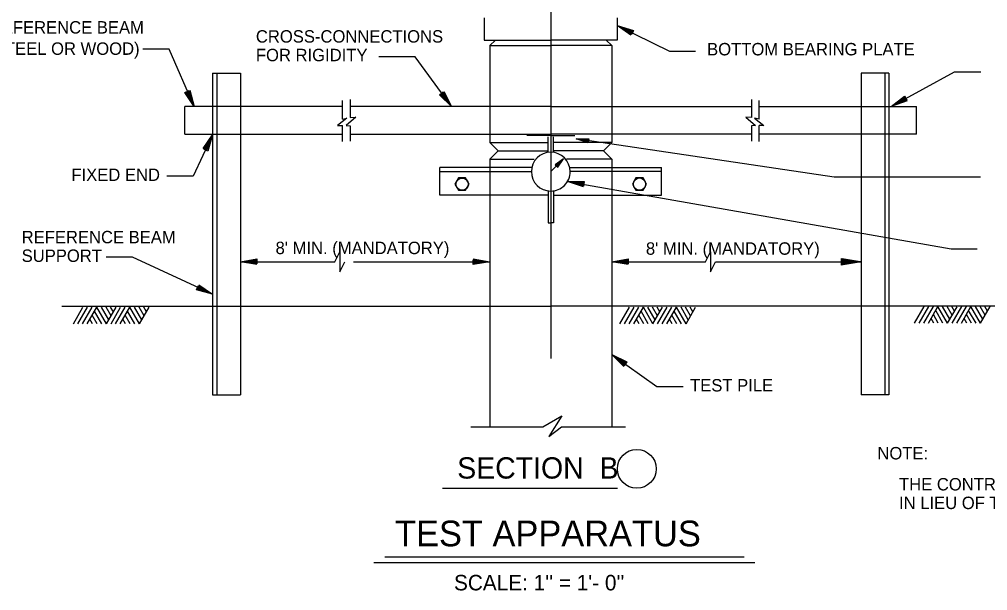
# Model space of a CAD drawing. Extents: x 22378.6 to 22422.6, y 22377.7 to 22411.7.
# Drawn here: x 22398.72 to 22409.64, y 22397.23 to 22403.67 of the extents above; entities that cross this region are included whole.
import ezdxf

# ---------------------------------------------------------------- set-up
doc = ezdxf.new("R2010")
doc.units = 0
for name, color, linetype in [('Level 1', 7, 'Continuous'), ('Level 10', 7, 'Continuous'), ('Level 2', 7, 'Continuous'), ('Level 3', 7, 'Continuous'), ('Level 4', 7, 'Continuous'), ('Level 7', 7, 'Continuous')]:
    doc.layers.add(name, color=color, linetype=linetype)

msp = doc.modelspace()

# ---------------------------------------------------------------- linework, layer by layer
at = {"layer": 'Level 1'}
for p, q in [((22404.71, 22409.083), (22404.71, 22399.845)), ((22405.46, 22403.6), (22405.46, 22403.6)), ((22405.507, 22403.577), (22405.507, 22403.577)), ((22400.667, 22402.734), (22400.667, 22402.734)), ((22402.36, 22402.544), (22402.36, 22402.755)), ((22402.447, 22402.765), (22402.447, 22402.562)), ((22406.972, 22402.765), (22406.972, 22402.562)), ((22407.06, 22402.544), (22407.06, 22402.755)), ((22400.688, 22402.686), (22400.688, 22402.686)), ((22403.56, 22402.728), (22403.56, 22402.728)), ((22403.591, 22402.686), (22403.591, 22402.686)), ((22408.548, 22402.686), (22408.548, 22402.686)), ((22408.594, 22402.711), (22408.594, 22402.711)), ((22402.41, 22402.556), (22402.307, 22402.471)), ((22402.36, 22402.544), (22402.41, 22402.556)), ((22402.511, 22402.568), (22402.402, 22402.471)), ((22402.447, 22402.562), (22402.511, 22402.568)), ((22406.909, 22402.568), (22407.018, 22402.471)), ((22406.972, 22402.562), (22406.909, 22402.568)), ((22407.06, 22402.544), (22407.009, 22402.556)), ((22407.009, 22402.556), (22407.113, 22402.471)), ((22402.307, 22402.471), (22402.36, 22402.473)), ((22402.36, 22402.292), (22402.36, 22402.473)), ((22402.402, 22402.471), (22402.447, 22402.468)), ((22402.447, 22402.468), (22402.447, 22402.297)), ((22407.018, 22402.471), (22406.972, 22402.468)), ((22406.972, 22402.468), (22406.972, 22402.297)), ((22407.06, 22402.292), (22407.06, 22402.473)), ((22407.113, 22402.471), (22407.06, 22402.473)), ((22400.875, 22402.319), (22400.875, 22402.319)), ((22400.897, 22402.366), (22400.897, 22402.366)), ((22404.996, 22402.32), (22404.996, 22402.32)), ((22405.034, 22402.315), (22405.034, 22402.315)), ((22404.022, 22402.28), (22404.669, 22402.28)), ((22405.397, 22402.28), (22404.749, 22402.28)), ((22404.022, 22402.093), (22404.524, 22402.093)), ((22404.854, 22402.096), (22404.761, 22402.03)), ((22404.764, 22402.029), (22404.836, 22402.081)), ((22404.854, 22402.096), (22404.774, 22402.016)), ((22404.836, 22402.081), (22404.776, 22402.021)), ((22404.839, 22402.079), (22404.779, 22402.018)), ((22404.787, 22402.006), (22404.839, 22402.079)), ((22404.788, 22402.003), (22404.854, 22402.096)), ((22405.397, 22402.093), (22404.888, 22402.093)), ((22404.761, 22402.03), (22404.788, 22402.003)), ((22404.774, 22402.019), (22404.764, 22402.029)), ((22404.767, 22402.029), (22404.82, 22402.067)), ((22404.776, 22402.021), (22404.767, 22402.029)), ((22404.771, 22402.028), (22404.797, 22402.048)), ((22404.776, 22402.024), (22404.771, 22402.028)), ((22404.82, 22402.067), (22404.776, 22402.024)), ((22404.797, 22402.048), (22404.776, 22402.027)), ((22404.777, 22402.016), (22404.787, 22402.006)), ((22404.779, 22402.018), (22404.787, 22402.01)), ((22404.825, 22402.062), (22404.782, 22402.018)), ((22404.782, 22402.018), (22404.787, 22402.013)), ((22404.806, 22402.039), (22404.785, 22402.018)), ((22404.787, 22402.01), (22404.825, 22402.062)), ((22404.787, 22402.013), (22404.806, 22402.039)), ((22403.67, 22401.881), (22403.63, 22401.811)), ((22403.75, 22401.881), (22403.67, 22401.881)), ((22403.79, 22401.811), (22403.75, 22401.881)), ((22405.67, 22401.881), (22405.63, 22401.812)), ((22405.75, 22401.881), (22405.67, 22401.881)), ((22405.79, 22401.812), (22405.75, 22401.881)), ((22403.63, 22401.811), (22403.67, 22401.742)), ((22403.75, 22401.742), (22403.79, 22401.811)), ((22404.899, 22401.842), (22404.899, 22401.842)), ((22404.95, 22401.833), (22404.95, 22401.833)), ((22405.63, 22401.812), (22405.67, 22401.742)), ((22405.75, 22401.742), (22405.79, 22401.812)), ((22403.67, 22401.742), (22403.75, 22401.742)), ((22405.67, 22401.742), (22405.75, 22401.742)), ((22401.21, 22400.936), (22402.276, 22400.936)), ((22401.21, 22400.936), (22401.21, 22400.936)), ((22401.262, 22400.936), (22401.262, 22400.936)), ((22402.486, 22400.936), (22404.022, 22400.936)), ((22403.97, 22400.936), (22403.97, 22400.936)), ((22404.022, 22400.936), (22404.022, 22400.936)), ((22405.397, 22400.936), (22406.455, 22400.936)), ((22405.397, 22400.936), (22405.397, 22400.936)), ((22405.449, 22400.936), (22405.449, 22400.936)), ((22406.568, 22400.936), (22408.21, 22400.936)), ((22407.985, 22400.974), (22407.985, 22400.899)), ((22407.985, 22400.974), (22408.21, 22400.936)), ((22408.21, 22400.936), (22407.985, 22400.936)), ((22408.21, 22400.936), (22407.985, 22400.899)), ((22407.988, 22400.904), (22408.176, 22400.934)), ((22407.989, 22400.933), (22407.988, 22400.904)), ((22407.99, 22400.967), (22407.989, 22400.94)), ((22407.989, 22400.94), (22408.177, 22400.939)), ((22408.177, 22400.939), (22407.994, 22400.968)), ((22407.994, 22400.968), (22407.994, 22400.943)), ((22407.994, 22400.943), (22408.135, 22400.942)), ((22408.176, 22400.934), (22407.994, 22400.933)), ((22407.994, 22400.933), (22407.994, 22400.909)), ((22407.994, 22400.909), (22408.133, 22400.93)), ((22408.135, 22400.942), (22407.999, 22400.962)), ((22407.999, 22400.962), (22407.999, 22400.948)), ((22407.999, 22400.948), (22408.072, 22400.947)), ((22408.133, 22400.93), (22407.999, 22400.928)), ((22407.999, 22400.928), (22407.999, 22400.914)), ((22407.999, 22400.914), (22408.073, 22400.924)), ((22408.073, 22400.924), (22408.004, 22400.924)), ((22408.004, 22400.924), (22408.004, 22400.919)), ((22408.004, 22400.919), (22408.025, 22400.92)), ((22408.072, 22400.947), (22408.005, 22400.958)), ((22408.005, 22400.958), (22408.005, 22400.952)), ((22408.005, 22400.952), (22408.026, 22400.952)), ((22400.85, 22400.592), (22400.85, 22400.592)), ((22400.897, 22400.57), (22400.897, 22400.57)), ((22399.327, 22400.235), (22399.435, 22400.423)), ((22399.379, 22400.235), (22399.487, 22400.423)), ((22399.431, 22400.235), (22399.539, 22400.423)), ((22399.483, 22400.235), (22399.591, 22400.423)), ((22399.596, 22400.235), (22399.539, 22400.333)), ((22399.648, 22400.235), (22399.565, 22400.378)), ((22399.7, 22400.235), (22399.591, 22400.423)), ((22399.726, 22400.28), (22399.643, 22400.423)), ((22399.752, 22400.325), (22399.695, 22400.423)), ((22399.7, 22400.235), (22399.808, 22400.423)), ((22399.778, 22400.37), (22399.747, 22400.423)), ((22399.752, 22400.235), (22399.86, 22400.423)), ((22399.803, 22400.235), (22399.912, 22400.423)), ((22399.855, 22400.235), (22399.964, 22400.423)), ((22399.968, 22400.235), (22399.912, 22400.333)), ((22400.02, 22400.235), (22399.938, 22400.378)), ((22400.072, 22400.235), (22399.964, 22400.423)), ((22400.098, 22400.28), (22400.016, 22400.423)), ((22400.124, 22400.325), (22400.068, 22400.423)), ((22400.072, 22400.235), (22400.18, 22400.423)), ((22400.15, 22400.37), (22400.12, 22400.423)), ((22405.49, 22400.235), (22405.598, 22400.423)), ((22405.542, 22400.235), (22405.65, 22400.423)), ((22405.594, 22400.235), (22405.702, 22400.423)), ((22405.646, 22400.235), (22405.754, 22400.423)), ((22405.758, 22400.235), (22405.702, 22400.333)), ((22405.81, 22400.235), (22405.728, 22400.378)), ((22405.862, 22400.235), (22405.754, 22400.423)), ((22405.888, 22400.28), (22405.806, 22400.423)), ((22405.914, 22400.325), (22405.858, 22400.423)), ((22405.862, 22400.235), (22405.971, 22400.423)), ((22405.94, 22400.37), (22405.91, 22400.423)), ((22405.914, 22400.235), (22406.023, 22400.423)), ((22405.966, 22400.235), (22406.075, 22400.423)), ((22406.018, 22400.235), (22406.127, 22400.423)), ((22406.131, 22400.235), (22406.075, 22400.333)), ((22406.183, 22400.235), (22406.101, 22400.378)), ((22406.235, 22400.235), (22406.127, 22400.423)), ((22406.261, 22400.28), (22406.179, 22400.423)), ((22406.287, 22400.325), (22406.231, 22400.423)), ((22406.235, 22400.235), (22406.343, 22400.423)), ((22406.313, 22400.37), (22406.283, 22400.423)), ((22408.812, 22400.242), (22408.92, 22400.43)), ((22408.864, 22400.242), (22408.972, 22400.43)), ((22408.916, 22400.242), (22409.024, 22400.43)), ((22408.968, 22400.242), (22409.076, 22400.43)), ((22409.08, 22400.242), (22409.024, 22400.34)), ((22409.132, 22400.242), (22409.05, 22400.385)), ((22409.184, 22400.242), (22409.076, 22400.43)), ((22409.21, 22400.287), (22409.128, 22400.43)), ((22409.236, 22400.332), (22409.18, 22400.43)), ((22409.184, 22400.242), (22409.292, 22400.429)), ((22409.262, 22400.377), (22409.232, 22400.43)), ((22409.236, 22400.242), (22409.344, 22400.43)), ((22409.288, 22400.242), (22409.396, 22400.43)), ((22409.34, 22400.242), (22409.448, 22400.43)), ((22409.453, 22400.242), (22409.396, 22400.34)), ((22409.505, 22400.242), (22409.422, 22400.385)), ((22409.557, 22400.242), (22409.448, 22400.43)), ((22409.583, 22400.287), (22409.5, 22400.43)), ((22409.609, 22400.332), (22409.552, 22400.43)), ((22409.557, 22400.242), (22409.665, 22400.43)), ((22409.635, 22400.377), (22409.604, 22400.43)), ((22399.544, 22400.235), (22399.513, 22400.288)), ((22399.916, 22400.235), (22399.886, 22400.288)), ((22405.707, 22400.235), (22405.676, 22400.288)), ((22406.079, 22400.235), (22406.049, 22400.288)), ((22409.028, 22400.242), (22408.998, 22400.295)), ((22409.401, 22400.242), (22409.37, 22400.295)), ((22405.397, 22399.889), (22405.397, 22399.889)), ((22405.44, 22399.859), (22405.44, 22399.859))]:
    msp.add_line(p, q, dxfattribs=at)
for points in [[(22405.46, 22403.6), (22406.047, 22403.311), (22406.343, 22403.311)], [(22405.614, 22403.489), (22405.46, 22403.6), (22405.641, 22403.545), (22405.618, 22403.497), (22405.507, 22403.577), (22405.63, 22403.539), (22405.615, 22403.509), (22405.551, 22403.555), (22405.618, 22403.534), (22405.612, 22403.521), (22405.598, 22403.532)], [(22400.688, 22402.686), (22400.408, 22403.333), (22400.112, 22403.333)], [(22403.591, 22402.686), (22403.182, 22403.248), (22402.771, 22403.248)], [(22408.548, 22402.686), (22409.264, 22403.077), (22409.56, 22403.077)], [(22400.642, 22402.87), (22400.688, 22402.686), (22400.585, 22402.846), (22400.634, 22402.867), (22400.667, 22402.734), (22400.598, 22402.842), (22400.629, 22402.856), (22400.648, 22402.78), (22400.61, 22402.839), (22400.623, 22402.845), (22400.627, 22402.828)], [(22403.506, 22402.856), (22403.591, 22402.686), (22403.456, 22402.819), (22403.498, 22402.851), (22403.56, 22402.728), (22403.468, 22402.819), (22403.496, 22402.839), (22403.531, 22402.769), (22403.481, 22402.818), (22403.493, 22402.826), (22403.5, 22402.811)], [(22408.727, 22402.749), (22408.548, 22402.686), (22408.697, 22402.803), (22408.723, 22402.757), (22408.594, 22402.711), (22408.695, 22402.791), (22408.711, 22402.761), (22408.637, 22402.735), (22408.693, 22402.778), (22408.699, 22402.766), (22408.683, 22402.76)], [(22400.897, 22402.366), (22400.676, 22401.9), (22400.379, 22401.9)], [(22400.789, 22402.211), (22400.897, 22402.366), (22400.845, 22402.184), (22400.797, 22402.207), (22400.875, 22402.319), (22400.839, 22402.195), (22400.809, 22402.21), (22400.854, 22402.274), (22400.834, 22402.207), (22400.821, 22402.213), (22400.831, 22402.227)], [(22405.131, 22402.277), (22404.996, 22402.32), (22405.138, 22402.323), (22405.132, 22402.283), (22405.034, 22402.315), (22405.131, 22402.316), (22405.127, 22402.291), (22405.071, 22402.309), (22405.124, 22402.31), (22405.122, 22402.299), (22405.11, 22402.303)], [(22409.555, 22401.888), (22407.906, 22401.888), (22404.996, 22402.32)], [(22404.899, 22401.842), (22409.223, 22401.082), (22409.519, 22401.082)], [(22405.078, 22401.779), (22404.899, 22401.842), (22405.088, 22401.84), (22405.079, 22401.788), (22404.95, 22401.833), (22405.079, 22401.832), (22405.073, 22401.798), (22404.999, 22401.824), (22405.069, 22401.823), (22405.067, 22401.809), (22405.051, 22401.815)], [(22400.897, 22400.57), (22399.993, 22400.988), (22399.696, 22400.988)], [(22402.276, 22400.936), (22402.332, 22401.049), (22402.332, 22400.824), (22402.389, 22400.936)], [(22406.455, 22400.936), (22406.511, 22401.049), (22406.511, 22400.824), (22406.568, 22400.936)], [(22401.397, 22400.905), (22401.21, 22400.936), (22401.397, 22400.967), (22401.397, 22400.914), (22401.262, 22400.936), (22401.389, 22400.957), (22401.389, 22400.923), (22401.312, 22400.936), (22401.381, 22400.947), (22401.381, 22400.933), (22401.364, 22400.936)], [(22403.835, 22400.967), (22404.022, 22400.936), (22403.835, 22400.905), (22403.835, 22400.958), (22403.97, 22400.936), (22403.843, 22400.915), (22403.843, 22400.949), (22403.92, 22400.936), (22403.851, 22400.925), (22403.851, 22400.939), (22403.868, 22400.936)], [(22405.584, 22400.905), (22405.397, 22400.936), (22405.584, 22400.967), (22405.584, 22400.914), (22405.449, 22400.936), (22405.576, 22400.957), (22405.576, 22400.923), (22405.499, 22400.936), (22405.568, 22400.947), (22405.568, 22400.933), (22405.551, 22400.936)], [(22400.741, 22400.677), (22400.897, 22400.57), (22400.715, 22400.62), (22400.737, 22400.669), (22400.85, 22400.592), (22400.726, 22400.626), (22400.74, 22400.657), (22400.805, 22400.613), (22400.738, 22400.632), (22400.743, 22400.645), (22400.758, 22400.635)], [(22405.397, 22399.889), (22405.907, 22399.529), (22406.203, 22399.529)], [(22405.532, 22399.756), (22405.397, 22399.889), (22405.568, 22399.807), (22405.537, 22399.763), (22405.44, 22399.859), (22405.556, 22399.803), (22405.536, 22399.775), (22405.481, 22399.83), (22405.543, 22399.799), (22405.535, 22399.788), (22405.523, 22399.8)]]:
    msp.add_lwpolyline(points, dxfattribs=at)
for centre in [(22403.71, 22401.811), (22405.71, 22401.812)]:
    msp.add_circle(centre, 0.0688, dxfattribs=at)
at = {"layer": 'Level 10'}
for p, q in [((22403.491, 22398.381), (22405.461, 22398.381)), ((22402.84, 22397.607), (22406.89, 22397.607)), ((22402.715, 22397.545), (22407.011, 22397.545))]:
    msp.add_line(p, q, dxfattribs=at)
at = {"layer": 'Level 2'}
for p, q in [((22404.022, 22403.374), (22404.71, 22403.374)), ((22405.397, 22403.374), (22404.71, 22403.374)), ((22400.944, 22403.061), (22400.944, 22400.436)), ((22408.476, 22403.061), (22408.476, 22400.436)), ((22401.21, 22402.686), (22400.897, 22402.686)), ((22404.022, 22402.686), (22404.022, 22402.374)), ((22405.397, 22402.686), (22405.397, 22402.374)), ((22408.21, 22402.686), (22408.522, 22402.686)), ((22400.897, 22402.374), (22401.21, 22402.374)), ((22404.679, 22402.169), (22404.679, 22402.344)), ((22404.741, 22402.169), (22404.741, 22402.344)), ((22408.522, 22402.374), (22408.21, 22402.374)), ((22404.71, 22401.952), (22404.854, 22402.096)), ((22404.022, 22401.999), (22404.022, 22401.686)), ((22405.397, 22401.999), (22405.397, 22401.686)), ((22403.46, 22401.952), (22404.491, 22401.952)), ((22405.96, 22401.952), (22404.929, 22401.952)), ((22404.679, 22401.736), (22404.679, 22401.374)), ((22404.741, 22401.736), (22404.741, 22401.374)), ((22404.679, 22401.374), (22404.71, 22401.374)), ((22404.741, 22401.374), (22404.71, 22401.374)), ((22399.197, 22400.436), (22404.71, 22400.436)), ((22400.897, 22400.436), (22400.897, 22399.436)), ((22400.944, 22400.436), (22400.944, 22399.436)), ((22401.21, 22400.436), (22401.21, 22399.436)), ((22404.022, 22400.436), (22404.022, 22399.073)), ((22410.223, 22400.436), (22404.71, 22400.436)), ((22405.397, 22400.436), (22405.397, 22399.073)), ((22408.21, 22400.436), (22408.21, 22399.436)), ((22408.476, 22400.436), (22408.476, 22399.436)), ((22408.522, 22400.436), (22408.522, 22399.436)), ((22400.897, 22399.436), (22401.21, 22399.436)), ((22408.522, 22399.436), (22408.21, 22399.436)), ((22404.62, 22399.073), (22404.834, 22399.197)), ((22404.834, 22399.197), (22404.69, 22398.967)), ((22403.807, 22399.073), (22404.62, 22399.073)), ((22404.69, 22398.967), (22404.831, 22399.073)), ((22404.831, 22399.073), (22405.554, 22399.073))]:
    msp.add_line(p, q, dxfattribs=at)
for start, end in [(90.0019, 180.0008), (0.0458, 89.9788), (180.0193, 269.9562), (269.9986, 360)]:
    msp.add_arc((22404.71, 22401.952), 0.219, start, end, dxfattribs=at)
at = {"layer": 'Level 3'}
for q in [(22404.44, 22402.358), (22404.98, 22402.358)]:
    msp.add_line((22404.71, 22402.358), q, dxfattribs=at)
msp.add_ellipse((22405.68, 22398.601), major_axis=(0, 0.219), ratio=0.999952, dxfattribs=at)
at = {"layer": 'Level 7'}
for p, q in [((22403.96, 22403.686), (22403.96, 22403.436)), ((22405.46, 22403.686), (22405.46, 22403.436)), ((22403.96, 22403.436), (22404.71, 22403.436)), ((22404.022, 22403.374), (22404.085, 22403.436)), ((22405.46, 22403.436), (22404.71, 22403.436)), ((22405.397, 22403.374), (22405.335, 22403.436)), ((22404.022, 22403.374), (22404.022, 22402.686)), ((22405.397, 22403.374), (22405.397, 22402.686)), ((22400.897, 22403.061), (22401.21, 22403.061)), ((22400.897, 22403.061), (22400.897, 22400.436)), ((22401.21, 22403.061), (22401.21, 22400.436)), ((22408.522, 22403.061), (22408.21, 22403.061)), ((22408.21, 22403.061), (22408.21, 22400.436)), ((22408.522, 22403.061), (22408.522, 22400.436)), ((22400.585, 22402.374), (22400.585, 22402.686)), ((22400.897, 22402.686), (22400.585, 22402.686)), ((22402.36, 22402.686), (22401.21, 22402.686)), ((22404.71, 22402.686), (22402.447, 22402.686)), ((22404.71, 22402.686), (22406.972, 22402.686)), ((22407.06, 22402.686), (22408.21, 22402.686)), ((22408.522, 22402.686), (22408.835, 22402.686)), ((22408.835, 22402.374), (22408.835, 22402.686)), ((22400.585, 22402.374), (22400.897, 22402.374)), ((22401.21, 22402.374), (22402.36, 22402.374)), ((22402.447, 22402.374), (22404.71, 22402.374)), ((22404.022, 22402.374), (22404.022, 22402.28)), ((22406.972, 22402.374), (22404.71, 22402.374)), ((22405.397, 22402.374), (22405.397, 22402.28)), ((22408.21, 22402.374), (22407.06, 22402.374)), ((22408.835, 22402.374), (22408.522, 22402.374)), ((22404.022, 22402.28), (22404.116, 22402.186)), ((22404.022, 22402.093), (22404.116, 22402.186)), ((22404.116, 22402.186), (22404.679, 22402.186)), ((22405.304, 22402.186), (22404.741, 22402.186)), ((22405.397, 22402.28), (22405.304, 22402.186)), ((22405.397, 22402.093), (22405.304, 22402.186)), ((22404.022, 22402.093), (22404.022, 22401.999)), ((22405.397, 22402.093), (22405.397, 22401.999)), ((22404.496, 22401.999), (22403.46, 22401.999)), ((22403.46, 22401.686), (22403.46, 22401.999)), ((22404.924, 22401.999), (22405.96, 22401.999)), ((22405.96, 22401.686), (22405.96, 22401.999)), ((22404.679, 22401.686), (22403.46, 22401.686)), ((22404.022, 22401.686), (22404.022, 22400.436)), ((22404.741, 22401.686), (22405.96, 22401.686)), ((22405.397, 22401.686), (22405.397, 22400.436))]:
    msp.add_line(p, q, dxfattribs=at)

# ---------------------------------------------------------------- texts
at = {"layer": 'Level 3'}
for s, height, p in [('SECTION  B', 0.24, (22403.655, 22398.491)), ('TEST APPARATUS', 0.29, (22402.954, 22397.727))]:
    msp.add_text(s, height=height, dxfattribs=at).set_placement(p)
at = {"layer": 'Level 4'}
for s, height, p in [('REFERENCE BEAM', 0.14, (22398.385, 22403.509)), ('CROSS-CONNECTIONS', 0.14, (22401.385, 22403.407)), ('(STEEL OR WOOD)', 0.14, (22398.368, 22403.269)), ('BOTTOM BEARING PLATE', 0.14, (22406.473, 22403.263)), ('FOR RIGIDITY', 0.14, (22401.385, 22403.197)), ('FIXED END', 0.14, (22399.305, 22401.847)), ('REFERENCE BEAM', 0.14, (22398.744, 22401.144)), ("8' MIN. (MANDATORY)", 0.14, (22401.607, 22401.022)), ("8' MIN. (MANDATORY)", 0.14, (22405.783, 22401.015)), ('SUPPORT', 0.14, (22398.744, 22400.934)), ('TEST PILE', 0.14, (22406.281, 22399.473)), ('NOTE:', 0.14, (22408.393, 22398.707)), ('THE CONTRACTOR HAS THE OPTION OF USING REACTION PILES', 0.14, (22408.637, 22398.357)), ('IN LIEU OF THE LOADING FRAME. (SEE SPECFICATIONS)', 0.14, (22408.637, 22398.147)), ("SCALE: 1'' = 1'- 0''", 0.175, (22403.619, 22397.23))]:
    msp.add_text(s, height=height, dxfattribs=at).set_placement(p)

doc.saveas('drawing.dxf')
